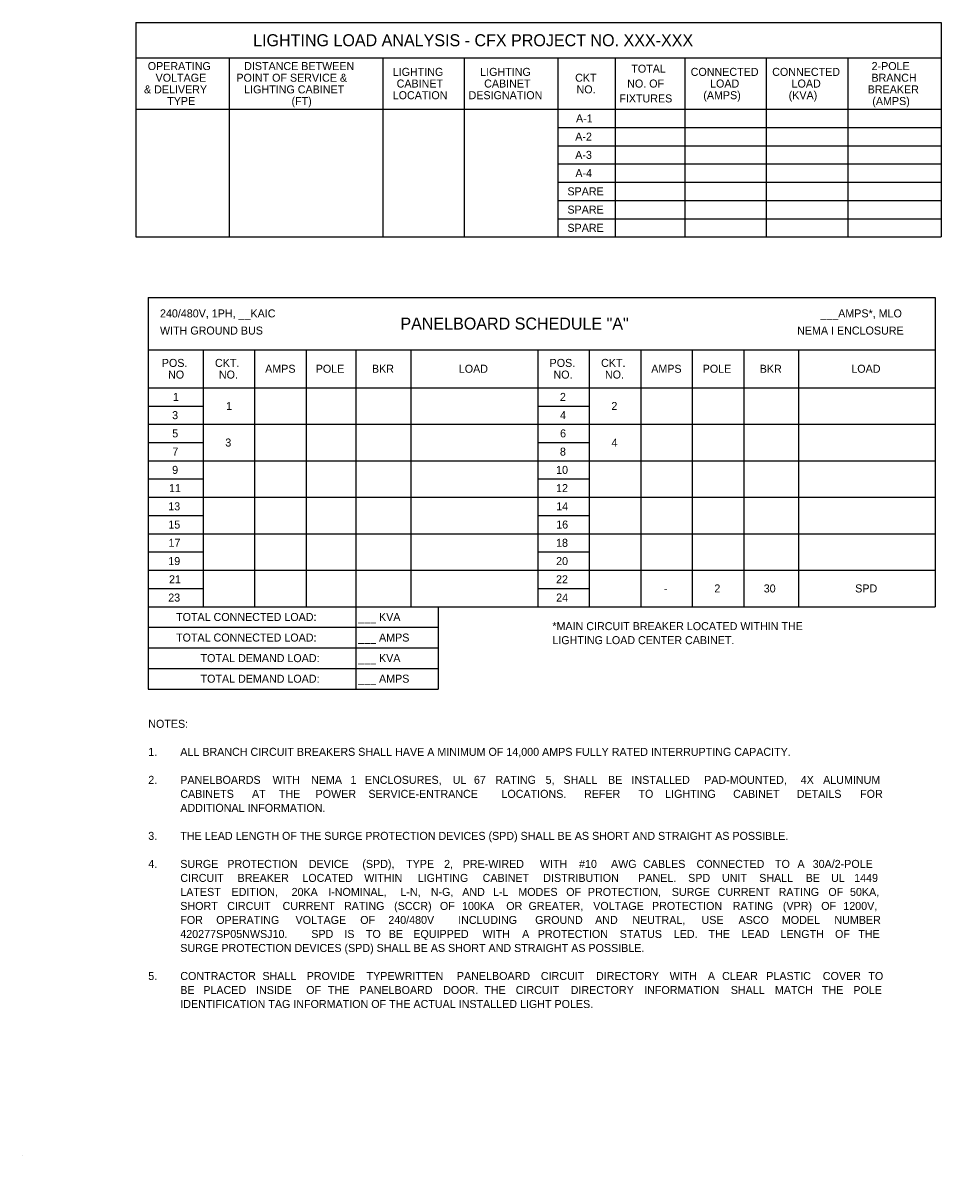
# Model space of a CAD drawing. Extents: x 856079 to 2148480, y 462635 to 2147771.
# Drawn here: x 2148464.67 to 2148472.7, y 2147761.57 to 2147771.47 of the extents above; entities that cross this region are included whole.
import ezdxf

# ---------------------------------------------------------------- set-up
doc = ezdxf.new("R2010")
doc.units = 0
for name, color, linetype in [('AdhocPoint_dp', 7, 'Continuous'), ('FLMap5', 7, 'Continuous'), ('SumBoxBorder_dp', 7, 'Continuous'), ('SumBoxLines_dp', 7, 'Continuous'), ('TextNotes', 7, 'Continuous')]:
    doc.layers.add(name, color=color, linetype=linetype)

msp = doc.modelspace()

# ---------------------------------------------------------------- linework, layer by layer
at = {"layer": 'AdhocPoint_dp'}
msp.add_line((2148464.6682, 2147761.5674), (2148464.6682, 2147761.5674), dxfattribs=at)
at = {"layer": 'SumBoxBorder_dp'}
for p, q in [((2148465.6565, 2147771.4724), (2148472.699, 2147771.4724)), ((2148465.6565, 2147771.4724), (2148465.6565, 2147769.5984)), ((2148472.699, 2147771.4724), (2148472.699, 2147769.5984)), ((2148465.6565, 2147771.1649), (2148472.699, 2147771.1649)), ((2148465.6565, 2147771.1649), (2148472.699, 2147771.1649)), ((2148465.6565, 2147769.5984), (2148472.699, 2147769.5984)), ((2148465.7662, 2147769.0699), (2148472.6437, 2147769.0699)), ((2148465.7662, 2147769.0699), (2148465.7662, 2147765.6454)), ((2148472.6437, 2147769.0699), (2148472.6437, 2147766.3654)), ((2148465.7662, 2147768.6124), (2148472.6437, 2147768.6124)), ((2148465.7662, 2147768.6124), (2148472.6437, 2147768.6124)), ((2148465.7662, 2147766.3654), (2148472.6437, 2147766.3654)), ((2148465.7662, 2147766.3654), (2148472.6437, 2147766.3654)), ((2148467.5812, 2147766.3654), (2148467.5812, 2147765.6454)), ((2148468.3012, 2147766.3654), (2148468.3012, 2147765.6454)), ((2148468.3012, 2147766.3654), (2148468.3012, 2147765.6454)), ((2148465.7662, 2147766.1854), (2148468.3012, 2147766.1854)), ((2148465.7662, 2147766.1854), (2148468.3012, 2147766.1854)), ((2148465.7662, 2147766.0054), (2148468.3012, 2147766.0054)), ((2148465.7662, 2147766.0054), (2148468.3012, 2147766.0054)), ((2148465.7662, 2147765.8254), (2148468.3012, 2147765.8254)), ((2148465.7662, 2147765.8254), (2148468.3012, 2147765.8254)), ((2148465.7662, 2147765.6454), (2148468.3012, 2147765.6454))]:
    msp.add_line(p, q, dxfattribs=at)
at = {"layer": 'SumBoxLines_dp'}
for p, q in [((2148466.474, 2147771.1649), (2148466.474, 2147769.5984)), ((2148466.474, 2147771.1649), (2148466.474, 2147769.5984)), ((2148467.8165, 2147771.1649), (2148467.8165, 2147769.5984)), ((2148467.8165, 2147771.1649), (2148467.8165, 2147769.5984)), ((2148468.529, 2147771.1649), (2148468.529, 2147769.5984)), ((2148468.529, 2147771.1649), (2148468.529, 2147769.5984)), ((2148469.3465, 2147771.1649), (2148469.3465, 2147769.5984)), ((2148469.3465, 2147771.1649), (2148469.3465, 2147769.5984)), ((2148469.849, 2147771.1649), (2148469.849, 2147769.5984)), ((2148469.849, 2147771.1649), (2148469.849, 2147769.5984)), ((2148470.4565, 2147771.1649), (2148470.4565, 2147769.5984)), ((2148470.4565, 2147771.1649), (2148470.4565, 2147769.5984)), ((2148471.169, 2147771.1649), (2148471.169, 2147769.5984)), ((2148471.169, 2147771.1649), (2148471.169, 2147769.5984)), ((2148471.8815, 2147771.1649), (2148471.8815, 2147769.5984)), ((2148471.8815, 2147771.1649), (2148471.8815, 2147769.5984)), ((2148465.6565, 2147770.7149), (2148472.699, 2147770.7149)), ((2148465.6565, 2147770.7149), (2148472.699, 2147770.7149)), ((2148469.3465, 2147770.5554), (2148472.699, 2147770.5554)), ((2148469.3465, 2147770.5554), (2148472.699, 2147770.5554)), ((2148469.3465, 2147770.3959), (2148472.699, 2147770.3959)), ((2148469.3465, 2147770.3959), (2148472.699, 2147770.3959)), ((2148469.3465, 2147770.2364), (2148472.699, 2147770.2364)), ((2148469.3465, 2147770.2364), (2148472.699, 2147770.2364)), ((2148469.3465, 2147770.0769), (2148472.699, 2147770.0769)), ((2148469.3465, 2147770.0769), (2148472.699, 2147770.0769)), ((2148469.3465, 2147769.9174), (2148472.699, 2147769.9174)), ((2148469.3465, 2147769.9174), (2148472.699, 2147769.9174)), ((2148469.3465, 2147769.7579), (2148472.699, 2147769.7579)), ((2148469.3465, 2147769.7579), (2148472.699, 2147769.7579)), ((2148466.2462, 2147768.6124), (2148466.2462, 2147766.3654)), ((2148466.2462, 2147768.6124), (2148466.2462, 2147766.3654)), ((2148466.6962, 2147768.6124), (2148466.6962, 2147766.3654)), ((2148466.6962, 2147768.6124), (2148466.6962, 2147766.3654)), ((2148467.1462, 2147768.6124), (2148467.1462, 2147766.3654)), ((2148467.1462, 2147768.6124), (2148467.1462, 2147766.3654)), ((2148467.5812, 2147768.6124), (2148467.5812, 2147766.3654)), ((2148467.5812, 2147768.6124), (2148467.5812, 2147766.3654)), ((2148468.0612, 2147768.6124), (2148468.0612, 2147766.3654)), ((2148468.0612, 2147768.6124), (2148468.0612, 2147766.3654)), ((2148469.1712, 2147768.6124), (2148469.1712, 2147766.3654)), ((2148469.1712, 2147768.6124), (2148469.1712, 2147766.3654)), ((2148469.6212, 2147768.6124), (2148469.6212, 2147766.3654)), ((2148469.6212, 2147768.6124), (2148469.6212, 2147766.3654)), ((2148470.0712, 2147768.6124), (2148470.0712, 2147766.3654)), ((2148470.0712, 2147768.6124), (2148470.0712, 2147766.3654)), ((2148470.5212, 2147768.6124), (2148470.5212, 2147766.3654)), ((2148470.5212, 2147768.6124), (2148470.5212, 2147766.3654)), ((2148470.9712, 2147768.6124), (2148470.9712, 2147766.3654)), ((2148470.9712, 2147768.6124), (2148470.9712, 2147766.3654)), ((2148471.4512, 2147768.6124), (2148471.4512, 2147766.3654)), ((2148471.4512, 2147768.6124), (2148471.4512, 2147766.3654)), ((2148465.7662, 2147768.2794), (2148472.6437, 2147768.2794)), ((2148465.7662, 2147768.2794), (2148472.6437, 2147768.2794)), ((2148465.7662, 2147768.1199), (2148466.2462, 2147768.1199)), ((2148465.7662, 2147768.1199), (2148466.2462, 2147768.1199)), ((2148469.1712, 2147768.1199), (2148469.6212, 2147768.1199)), ((2148465.7662, 2147767.9604), (2148472.6437, 2147767.9604)), ((2148465.7662, 2147767.9604), (2148472.6437, 2147767.9604)), ((2148465.7662, 2147767.8009), (2148466.2462, 2147767.8009)), ((2148465.7662, 2147767.8009), (2148466.2462, 2147767.8009)), ((2148469.1712, 2147767.8009), (2148469.6212, 2147767.8009)), ((2148469.1712, 2147767.8009), (2148469.6212, 2147767.8009)), ((2148465.7662, 2147767.6414), (2148469.1712, 2147767.6414)), ((2148465.7662, 2147767.6414), (2148472.6437, 2147767.6414)), ((2148469.6212, 2147767.6414), (2148472.6437, 2147767.6414)), ((2148465.7662, 2147767.4819), (2148466.2462, 2147767.4819)), ((2148465.7662, 2147767.4819), (2148466.2462, 2147767.4819)), ((2148469.1712, 2147767.4819), (2148469.6212, 2147767.4819)), ((2148469.1712, 2147767.4819), (2148469.6212, 2147767.4819)), ((2148465.7662, 2147767.3224), (2148472.6437, 2147767.3224)), ((2148465.7662, 2147767.3224), (2148472.6437, 2147767.3224)), ((2148465.7662, 2147767.1629), (2148466.2462, 2147767.1629)), ((2148465.7662, 2147767.1629), (2148466.2462, 2147767.1629)), ((2148469.1712, 2147767.1629), (2148469.6212, 2147767.1629)), ((2148465.7662, 2147767.0034), (2148472.6437, 2147767.0034)), ((2148465.7662, 2147767.0034), (2148472.6437, 2147767.0034)), ((2148465.7662, 2147766.8439), (2148466.2462, 2147766.8439)), ((2148465.7662, 2147766.8439), (2148466.2462, 2147766.8439)), ((2148469.1712, 2147766.8439), (2148469.6212, 2147766.8439)), ((2148469.1712, 2147766.8439), (2148469.6212, 2147766.8439)), ((2148465.7662, 2147766.6844), (2148469.1712, 2147766.6844)), ((2148465.7662, 2147766.6844), (2148472.6437, 2147766.6844)), ((2148469.6212, 2147766.6844), (2148472.6437, 2147766.6844)), ((2148465.7662, 2147766.5249), (2148466.2462, 2147766.5249)), ((2148465.7662, 2147766.5249), (2148466.2462, 2147766.5249)), ((2148469.1712, 2147766.5249), (2148469.6212, 2147766.5249)), ((2148469.1712, 2147766.5249), (2148469.6212, 2147766.5249))]:
    msp.add_line(p, q, dxfattribs=at)

# ---------------------------------------------------------------- texts
at = {"layer": 'FLMap5'}
for s, height, p in [('LIGHTING LOAD ANALYSIS - CFX PROJECT NO. XXX-XXX', 0.105, (2148466.6829, 2147771.2662)), ('OPERATING', 0.07, (2148465.7617, 2147771.0579)), ('DISTANCE BETWEEN', 0.07, (2148466.6045, 2147771.0579)), ('TOTAL', 0.07, (2148469.9891, 2147771.0349)), ('2-POLE', 0.07, (2148472.0893, 2147771.0579)), ('VOLTAGE', 0.07, (2148465.8304, 2147770.9559)), ('POINT OF SERVICE &', 0.07, (2148466.5368, 2147770.9559)), ('LIGHTING', 0.07, (2148467.9031, 2147771.0069)), ('LIGHTING', 0.07, (2148468.6681, 2147771.0069)), ('CKT', 0.07, (2148469.4979, 2147770.9559)), ('CONNECTED', 0.07, (2148470.5081, 2147771.0069)), ('CONNECTED', 0.07, (2148471.2206, 2147771.0069)), ('BRANCH', 0.07, (2148472.0883, 2147770.9559)), ('& DELIVERY', 0.07, (2148465.7289, 2147770.8539)), ('LIGHTING CABINET', 0.07, (2148466.605, 2147770.8539)), ('CABINET', 0.07, (2148467.9374, 2147770.9049)), ('CABINET', 0.07, (2148468.7024, 2147770.9049)), ('NO.', 0.07, (2148469.5101, 2147770.8539)), ('NO. OF', 0.07, (2148469.9528, 2147770.9049)), ('LOAD', 0.07, (2148470.6775, 2147770.9049)), ('LOAD', 0.07, (2148471.39, 2147770.9049)), ('BREAKER', 0.07, (2148472.0553, 2147770.8539)), ('TYPE', 0.07, (2148465.932, 2147770.7519)), ('(FT)', 0.07, (2148467.0184, 2147770.7519)), ('LOCATION', 0.07, (2148467.9031, 2147770.8029)), ('DESIGNATION', 0.07, (2148468.5664, 2147770.8029)), ('FIXTURES', 0.07, (2148469.8842, 2147770.7749)), ('(AMPS)', 0.07, (2148470.6182, 2147770.8029)), ('(KVA)', 0.07, (2148471.3646, 2147770.8029)), ('(AMPS)', 0.07, (2148472.0957, 2147770.7519)), ('A-1', 0.07, (2148469.5054, 2147770.6002)), ('A-2', 0.07, (2148469.4986, 2147770.4407)), ('A-3', 0.07, (2148469.4986, 2147770.2812)), ('A-4', 0.07, (2148469.5, 2147770.1217)), ('SPARE', 0.07, (2148469.4306, 2147769.9622)), ('SPARE', 0.07, (2148469.4306, 2147769.8027)), ('SPARE', 0.07, (2148469.4306, 2147769.6432)), ('240/480V, 1PH, __KAIC', 0.07, (2148465.8687, 2147768.8949)), ('___AMPS*, MLO', 0.07, (2148471.6413, 2147768.8949)), ('WITH GROUND BUS', 0.07, (2148465.8687, 2147768.7449)), ('PANELBOARD SCHEDULE "A"', 0.105, (2148467.9705, 2147768.7887)), ('NEMA I ENCLOSURE', 0.07, (2148471.4385, 2147768.7449)), ('POS.', 0.07, (2148465.8847, 2147768.4619)), ('CKT.', 0.07, (2148466.3497, 2147768.4619)), ('POS.', 0.07, (2148469.2747, 2147768.4619)), ('CKT.', 0.07, (2148469.7247, 2147768.4619)), ('NO', 0.07, (2148465.9394, 2147768.3599)), ('NO.', 0.07, (2148466.3835, 2147768.3599)), ('AMPS', 0.07, (2148466.7881, 2147768.4109)), ('POLE', 0.07, (2148467.2304, 2147768.4109)), ('BKR', 0.07, (2148467.7217, 2147768.4109)), ('LOAD', 0.07, (2148468.481, 2147768.4109)), ('NO.', 0.07, (2148469.3085, 2147768.3599)), ('NO.', 0.07, (2148469.7585, 2147768.3599)), ('AMPS', 0.07, (2148470.1631, 2147768.4109)), ('POLE', 0.07, (2148470.6129, 2147768.4109)), ('BKR', 0.07, (2148471.1117, 2147768.4109)), ('LOAD', 0.07, (2148471.9122, 2147768.4109)), ('1', 0.07, (2148465.9815, 2147768.1647)), ('2', 0.07, (2148469.3648, 2147768.1647)), ('1', 0.07, (2148466.4465, 2147768.0849)), ('2', 0.07, (2148469.8148, 2147768.0849)), ('3', 0.07, (2148465.9748, 2147768.0052)), ('4', 0.07, (2148469.3662, 2147768.0052)), ('5', 0.07, (2148465.9757, 2147767.8457)), ('6', 0.07, (2148469.3662, 2147767.8457)), ('3', 0.07, (2148466.4398, 2147767.7659)), ('4', 0.07, (2148469.8162, 2147767.7659)), ('7', 0.07, (2148465.9768, 2147767.6862)), ('8', 0.07, (2148469.365, 2147767.6862)), ('9', 0.07, (2148465.9752, 2147767.5267)), ('10', 0.07, (2148469.3315, 2147767.5267)), ('11', 0.07, (2148465.9477, 2147767.3672)), ('12', 0.07, (2148469.3309, 2147767.3672)), ('13', 0.07, (2148465.9409, 2147767.2077)), ('14', 0.07, (2148469.3323, 2147767.2077)), ('16', 0.07, (2148469.3323, 2147767.0482)), ('15', 0.07, (2148465.9418, 2147767.0482)), ('17', 0.07, (2148465.9429, 2147766.8887)), ('18', 0.07, (2148469.3312, 2147766.8887)), ('19', 0.07, (2148465.9413, 2147766.7292)), ('20', 0.07, (2148469.3315, 2147766.7292)), ('21', 0.07, (2148465.9477, 2147766.5697)), ('22', 0.07, (2148469.3309, 2147766.5697)), ('2', 0.07, (2148470.7148, 2147766.4899)), ('30', 0.07, (2148471.1465, 2147766.4899)), ('SPD', 0.07, (2148471.9461, 2147766.4899)), ('23', 0.07, (2148465.9409, 2147766.4102)), ('24', 0.07, (2148469.3323, 2147766.4102)), ('-', 0.07, (2148470.2727, 2147766.4899)), ('TOTAL CONNECTED LOAD:', 0.07, (2148466.0093, 2147766.2404)), ('___ KVA', 0.07, (2148467.6012, 2147766.2404)), ('TOTAL CONNECTED LOAD:', 0.07, (2148466.0093, 2147766.0604)), ('___ AMPS', 0.07, (2148467.6012, 2147766.0604)), ('TOTAL DEMAND LOAD:', 0.07, (2148466.2233, 2147765.8804)), ('___ KVA', 0.07, (2148467.6012, 2147765.8804)), ('TOTAL DEMAND LOAD:', 0.07, (2148466.2233, 2147765.7004)), ('___ AMPS', 0.07, (2148467.6012, 2147765.7004))]:
    msp.add_text(s, height=height, dxfattribs=at).set_placement(p)
at = {"layer": 'TextNotes'}
for s, p in [('*MAIN CIRCUIT BREAKER LOCATED WITHIN THE', (2148469.2988, 2147766.1602)), ('LIGHTING LOAD CENTER CABINET.', (2148469.2988, 2147766.0377)), ('NOTES:', (2148465.7662, 2147765.3059)), ('1.', (2148465.7662, 2147765.0609)), ('ALL BRANCH CIRCUIT BREAKERS SHALL HAVE A MINIMUM OF 14,000 AMPS FULLY RATED INTERRUPTING CAPACITY.', (2148466.0462, 2147765.0609)), ('2.', (2148465.7662, 2147764.8159)), ('PANELBOARDS ', (2148466.0462, 2147764.8159)), ('WITH ', (2148466.8531, 2147764.8159)), ('NEMA ', (2148467.1892, 2147764.8159)), ('1 ', (2148467.5342, 2147764.8159)), ('ENCLOSURES, ', (2148467.6599, 2147764.8159)), ('UL ', (2148468.4276, 2147764.8159)), ('67 ', (2148468.613, 2147764.8159)), ('RATING ', (2148468.8015, 2147764.8159)), ('5, ', (2148469.2397, 2147764.8159)), ('SHALL ', (2148469.396, 2147764.8159)), ('BE ', (2148469.7854, 2147764.8159)), ('INSTALLED ', (2148469.9904, 2147764.8159)), ('PAD-MOUNTED, ', (2148470.6258, 2147764.8159)), ('4X ', (2148471.4699, 2147764.8159)), ('ALUMINUM ', (2148471.6658, 2147764.8159)), ('CABINETS ', (2148466.0462, 2147764.6934)), ('AT ', (2148466.6733, 2147764.6934)), ('THE ', (2148466.9072, 2147764.6934)), ('POWER ', (2148467.229, 2147764.6934)), ('SERVICE-ENTRANCE ', (2148467.691, 2147764.6934)), ('LOCATIONS. ', (2148468.8538, 2147764.6934)), (' REFER ', (2148469.5492, 2147764.6934)), ('TO ', (2148470.0517, 2147764.6934)), ('LIGHTING ', (2148470.2851, 2147764.6934)), ('CABINET ', (2148470.8792, 2147764.6934)), ('DETAILS ', (2148471.4355, 2147764.6934)), ('FOR ', (2148471.9891, 2147764.6934)), ('ADDITIONAL INFORMATION.', (2148466.0462, 2147764.5709)), ('3.', (2148465.7662, 2147764.3259)), ('THE LEAD LENGTH OF THE SURGE PROTECTION DEVICES (SPD) SHALL BE AS SHORT AND STRAIGHT AS POSSIBLE.', (2148466.0462, 2147764.3259)), ('4.', (2148465.7662, 2147764.0809)), ('SURGE ', (2148466.0462, 2147764.0809)), ('PROTECTION ', (2148466.4572, 2147764.0809)), ('DEVICE ', (2148467.17, 2147764.0809)), ('(SPD), ', (2148467.6377, 2147764.0809)), ('TYPE ', (2148468.0205, 2147764.0809)), ('2, ', (2148468.3525, 2147764.0809)), ('PRE-WIRED ', (2148468.5148, 2147764.0809)), ('WITH ', (2148469.1899, 2147764.0809)), ('#10 ', (2148469.5321, 2147764.0809)), ('AWG ', (2148469.8114, 2147764.0809)), ('CABLES ', (2148470.0921, 2147764.0809)), ('CONNECTED ', (2148470.5591, 2147764.0809)), ('TO ', (2148471.245, 2147764.0809)), ('A ', (2148471.4413, 2147764.0809)), ('30A/2-POLE ', (2148471.5744, 2147764.0809)), ('CIRCUIT ', (2148466.0462, 2147763.9584)), ('BREAKER ', (2148466.5472, 2147763.9584)), ('LOCATED ', (2148467.1135, 2147763.9584)), ('WITHIN ', (2148467.654, 2147763.9584)), ('LIGHTING ', (2148468.1216, 2147763.9584)), ('CABINET ', (2148468.6893, 2147763.9584)), ('DISTRIBUTION ', (2148469.2193, 2147763.9584)), ('PANEL. ', (2148470.0496, 2147763.9584)), ('SPD ', (2148470.4858, 2147763.9584)), ('UNIT ', (2148470.7817, 2147763.9584)), ('SHALL ', (2148471.1069, 2147763.9584)), ('BE ', (2148471.5131, 2147763.9584)), ('UL ', (2148471.7348, 2147763.9584)), ('1449 ', (2148471.937, 2147763.9584)), ('LATEST ', (2148466.0462, 2147763.8359)), ('EDITION, ', (2148466.4942, 2147763.8359)), ('20KA ', (2148467.0192, 2147763.8359)), ('I-NOMINAL, ', (2148467.3393, 2147763.8359)), ('L-N, ', (2148467.9703, 2147763.8359)), ('N-G, ', (2148468.2361, 2147763.8359)), ('AND ', (2148468.5106, 2147763.8359)), ('L-L ', (2148468.7797, 2147763.8359)), ('MODES ', (2148469.0011, 2147763.8359)), ('OF ', (2148469.4198, 2147763.8359)), ('PROTECTION, ', (2148469.6094, 2147763.8359)), ('SURGE ', (2148470.3427, 2147763.8359)), ('CURRENT ', (2148470.7435, 2147763.8359)), ('RATING ', (2148471.2769, 2147763.8359)), ('OF ', (2148471.7111, 2147763.8359)), ('50KA, ', (2148471.9007, 2147763.8359)), ('SHORT ', (2148466.0462, 2147763.7134)), ('CIRCUIT ', (2148466.4564, 2147763.7134)), ('CURRENT ', (2148466.9403, 2147763.7134)), ('RATING ', (2148467.4775, 2147763.7134)), ('(SCCR) ', (2148467.9154, 2147763.7134)), ('OF ', (2148468.3157, 2147763.7134)), ('100KA ', (2148468.5091, 2147763.7134)), ('OR ', (2148468.8958, 2147763.7134)), ('GREATER, ', (2148469.0907, 2147763.7134)), ('VOLTAGE ', (2148469.656, 2147763.7134)), ('PROTECTION ', (2148470.1694, 2147763.7134)), ('RATING ', (2148470.8758, 2147763.7134)), ('(VPR) ', (2148471.3137, 2147763.7134)), ('OF ', (2148471.649, 2147763.7134)), ('1200V, ', (2148471.8424, 2147763.7134)), ('FOR ', (2148466.0462, 2147763.5909)), ('OPERATING ', (2148466.3603, 2147763.5909)), ('VOLTAGE ', (2148467.0539, 2147763.5909)), ('OF ', (2148467.6192, 2147763.5909)), ('240/480V ', (2148467.8646, 2147763.5909)), ('INCLUDING ', (2148468.4754, 2147763.5909)), ('GROUND ', (2148469.1484, 2147763.5909)), ('AND ', (2148469.6727, 2147763.5909)), ('NEUTRAL, ', (2148469.9976, 2147763.5909)), ('USE ', (2148470.6026, 2147763.5909)), ('ASCO ', (2148470.9263, 2147763.5909)), ('MODEL ', (2148471.305, 2147763.5909)), ('NUMBER ', (2148471.7642, 2147763.5909)), ('420277SP05NWSJ10. ', (2148466.0462, 2147763.4684)), ('SPD ', (2148467.1915, 2147763.4684)), ('IS ', (2148467.4803, 2147763.4684)), ('TO ', (2148467.6688, 2147763.4684)), ('BE ', (2148467.8687, 2147763.4684)), ('EQUIPPED ', (2148468.0833, 2147763.4684)), ('WITH ', (2148468.6887, 2147763.4684)), ('A ', (2148469.0345, 2147763.4684)), ('PROTECTION ', (2148469.1711, 2147763.4684)), ('STATUS ', (2148469.8875, 2147763.4684)), ('LED. ', (2148470.3602, 2147763.4684)), ('THE ', (2148470.6639, 2147763.4684)), ('LEAD ', (2148470.9522, 2147763.4684)), ('LENGTH ', (2148471.2925, 2147763.4684)), ('OF ', (2148471.7697, 2147763.4684)), ('THE ', (2148471.973, 2147763.4684)), ('SURGE PROTECTION DEVICES (SPD) SHALL BE AS SHORT AND STRAIGHT AS POSSIBLE.', (2148466.0462, 2147763.3459)), ('5.', (2148465.7662, 2147763.1009)), ('CONTRACTOR ', (2148466.0462, 2147763.1009)), ('SHALL ', (2148466.764, 2147763.1009)), ('PROVIDE ', (2148467.1512, 2147763.1009)), ('TYPEWRITTEN ', (2148467.6747, 2147763.1009)), ('PANELBOARD ', (2148468.4642, 2147763.1009)), ('CIRCUIT ', (2148469.1981, 2147763.1009)), ('DIRECTORY ', (2148469.6801, 2147763.1009)), ('WITH ', (2148470.3241, 2147763.1009)), ('A ', (2148470.658, 2147763.1009)), ('CLEAR ', (2148470.7827, 2147763.1009)), ('PLASTIC ', (2148471.1687, 2147763.1009)), ('COVER ', (2148471.663, 2147763.1009)), ('TO ', (2148472.0613, 2147763.1009)), ('BE ', (2148466.0462, 2147762.9784)), ('PLACED ', (2148466.2474, 2147762.9784)), ('INSIDE ', (2148466.7086, 2147762.9784)), ('OF ', (2148467.1467, 2147762.9784)), ('THE ', (2148467.3367, 2147762.9784)), ('PANELBOARD ', (2148467.6116, 2147762.9784)), ('DOOR. ', (2148468.344, 2147762.9784)), ('THE ', (2148468.7037, 2147762.9784)), ('CIRCUIT ', (2148468.9785, 2147762.9784)), ('DIRECTORY ', (2148469.4591, 2147762.9784)), ('INFORMATION ', (2148470.1016, 2147762.9784)), ('SHALL ', (2148470.8585, 2147762.9784)), ('MATCH ', (2148471.2442, 2147762.9784)), ('THE ', (2148471.6548, 2147762.9784)), ('POLE ', (2148471.9297, 2147762.9784)), ('IDENTIFICATION TAG INFORMATION OF THE ACTUAL INSTALLED LIGHT POLES.', (2148466.0462, 2147762.8559))]:
    msp.add_text(s, height=0.07, dxfattribs=at).set_placement(p)

doc.saveas('drawing.dxf')
